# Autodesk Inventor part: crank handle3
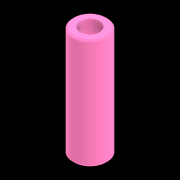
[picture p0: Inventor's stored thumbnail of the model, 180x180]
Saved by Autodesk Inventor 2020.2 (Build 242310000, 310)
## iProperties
Category: 11
Manager: PART
Company: 23
Created: 2020-10
Part Number: crank handle3
Material: Generic
Document SubType Name: Modeling
Designer: Apardo
Density: 1 g/cm^3
Appearance: Pink
Vendor: 11
Project: PLATE ROLLING MACHINE
Cost Center: 1
Engineer: WOOD
Stock Number: 2.3
Description: crank handle3
Engr Approved By: D. JAEGER
Author: Apardo
Revision Number: 1.0
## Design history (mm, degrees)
sketch "Sketch1"
  geometry: L1 (0, 0)-(0, 80.75); L2 (-7, 40)-(-7, 24); L3 (-7, 24)-(-4.25, 24); L4 (-4.25, 24)-(-4.25, -40); L5 (-4.25, -40)-(-12.5, -40); L6 (-12.5, -40)-(-12.5, 40); L7 (-12.5, 40)-(-7, 40)
  constraints: 14 end point, 5 perpendicular, 2 vertical
  dimensions: "d0" = 8.5 diameter of L4 L1; "d1" = 80 distance of L5.end L6.end; "d2" = 40 distance from line of L5 L1.start (= 0.5 x d1); "d3" = 25 diameter of L6 L1; "d4" = 14 diameter of L2 L1; "d5" = 16 distance of L2.start L2.end
revolve "Revolution1" sketch "Sketch1" stored, may be unused: angle "d6" = 90 deg
chamfer "Chamfer1" distance "d7" = 1; stored, may be unused: second distance "d8" = 2, angle "d9" = 45 deg
body "Solid1"
